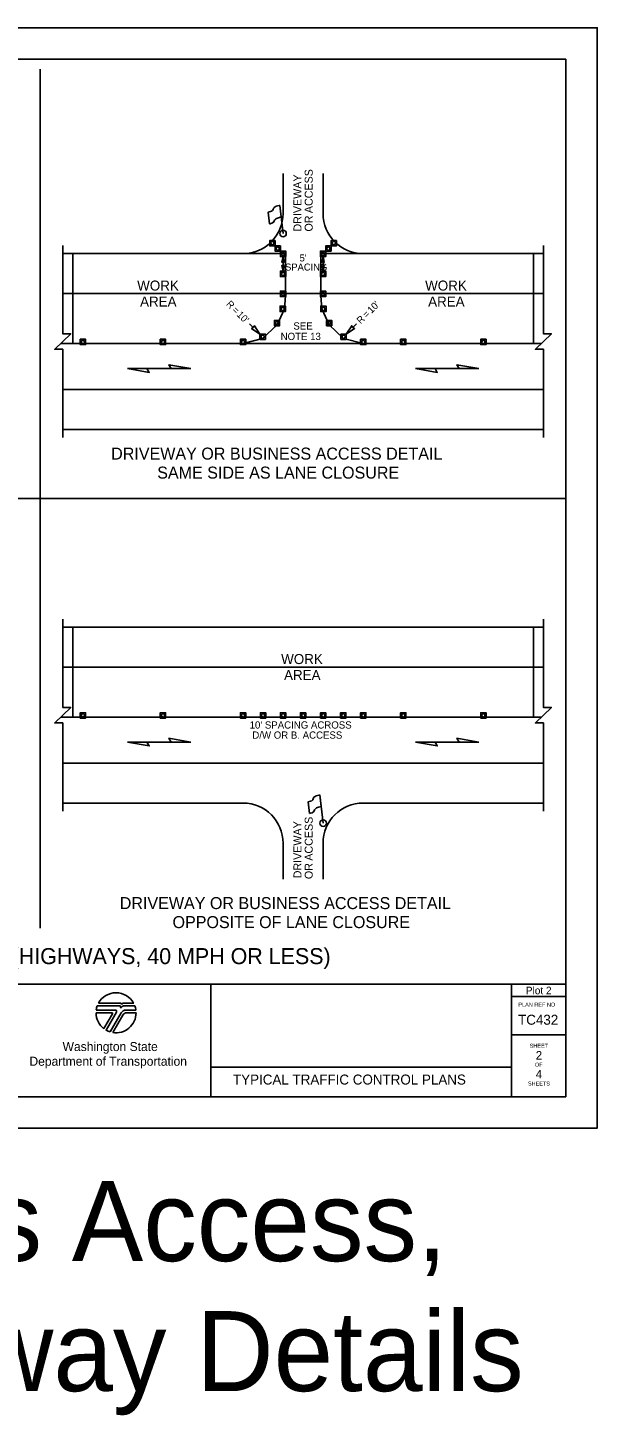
# Model space of a CAD drawing. Extents: x 99999.1 to 100095.7, y 99995 to 100010.7.
# Drawn here: x 100030.38 to 100036.06, y 99996.82 to 100010.69 of the extents above; entities that cross this region are included whole.
import ezdxf

# ---------------------------------------------------------------- set-up
doc = ezdxf.new("R2010")
doc.units = 0
for name, color, linetype in [('RD_ED_DrivewayEdge', 7, 'Continuous'), ('RD_ED_ShoulderPavedEdge', 7, 'Continuous'), ('RD_MK_LineEdgeWhite', 7, 'Continuous'), ('RD_MK_LineSkipCenter', 7, 'Continuous'), ('SH_DE_DetailHeading1Text', 7, 'Continuous'), ('SH_DE_DetailHeading2Text', 7, 'Continuous'), ('SH_GI_PlotLimits', 7, 'Continuous'), ('SH_GI_SheetBorder', 7, 'Continuous'), ('SH_GI_SheetLocationText', 7, 'Continuous'), ('SH_GI_SheetTextInCells', 7, 'Continuous'), ('SH_GI_TitleBlockText', 7, 'Continuous'), ('SH_GI_WSDOTLogo', 7, 'Continuous'), ('TR_WZ_FlaggingStation', 7, 'Continuous'), ('TR_WZ_TrafficCone', 7, 'Continuous'), ('TR_WZ_WorkAreaLabel', 7, 'Continuous'), ('TR_WZ_WorkZoneDetails', 7, 'Continuous'), ('TR_WZ_WorkZoneTextCurrent', 7, 'Continuous')]:
    doc.layers.add(name, color=color, linetype=linetype)

msp = doc.modelspace()

# ---------------------------------------------------------------- linework, layer by layer
at = {"layer": 'RD_ED_DrivewayEdge'}
for p, q in [((100032.925, 100008.83), (100032.925, 100009.23)), ((100033.325, 100008.83), (100033.325, 100009.23)), ((100032.925, 100002.536), (100032.925, 100002.176)), ((100033.325, 100002.536), (100033.325, 100002.176))]:
    msp.add_line(p, q, dxfattribs=at)
for centre, start, end in [((100032.525, 100008.83), 270, 0), ((100033.725, 100008.83), 180, 270), ((100032.525, 100002.536), 0, 90), ((100033.725, 100002.536), 90, 180)]:
    msp.add_arc(centre, 0.4, start, end, dxfattribs=at)
at = {"layer": 'RD_ED_ShoulderPavedEdge'}
for p, q in [((100030.725, 100008.43), (100032.525, 100008.43)), ((100033.725, 100008.43), (100035.525, 100008.43)), ((100030.725, 100006.67), (100035.525, 100006.67)), ((100030.725, 100004.696), (100035.525, 100004.696)), ((100030.725, 100002.936), (100032.525, 100002.936)), ((100033.725, 100002.936), (100035.525, 100002.936))]:
    msp.add_line(p, q, dxfattribs=at)
at = {"layer": 'RD_MK_LineEdgeWhite'}
for p, q in [((100030.725, 100008.03), (100035.525, 100008.03)), ((100030.725, 100007.07), (100035.525, 100007.07)), ((100030.725, 100004.296), (100035.525, 100004.296)), ((100030.725, 100003.336), (100035.525, 100003.336))]:
    msp.add_line(p, q, dxfattribs=at)
at = {"layer": 'RD_MK_LineSkipCenter'}
for points in [[(100035.504, 100007.53), (100030.704, 100007.53)], [(100035.504, 100003.796), (100030.704, 100003.796)]]:
    msp.add_lwpolyline(points, dxfattribs=at)
at = {"layer": 'SH_GI_PlotLimits'}
msp.add_lwpolyline([(100019.062, 99999.687), (100036.062, 99999.687), (100036.062, 100010.687), (100019.062, 100010.687)], close=True, dxfattribs=at)
at = {"layer": 'SH_GI_SheetBorder'}
for p, q in [((100020, 100010.375), (100035.75, 100010.375)), ((100035.75, 100010.375), (100035.75, 100000)), ((100020, 100001.126), (100035.75, 100001.126)), ((100032.205, 100001.126), (100032.205, 100000)), ((100035.208, 100001.126), (100035.208, 100000)), ((100035.208, 100001.001), (100035.75, 100001.001)), ((100035.208, 100000.618), (100035.75, 100000.618)), ((100032.205, 100000.295), (100035.208, 100000.295)), ((100020, 100000), (100035.75, 100000))]:
    msp.add_line(p, q, dxfattribs=at)
at = {"layer": 'SH_GI_WSDOTLogo'}
for p, q in [((100031.059, 100000.866), (100031.25, 100000.866)), ((100031.289, 100000.909), (100031.07, 100000.909)), ((100031.303, 100000.935), (100031.081, 100000.935)), ((100031.433, 100000.935), (100031.335, 100000.935)), ((100031.445, 100000.909), (100031.343, 100000.909)), ((100031.343, 100000.909), (100031.343, 100000.909)), ((100031.356, 100000.866), (100031.456, 100000.866)), ((100031.057, 100000.84), (100031.215, 100000.84)), ((100031.222, 100000.828), (100031.136, 100000.681)), ((100031.261, 100000.846), (100031.157, 100000.667)), ((100031.199, 100000.649), (100031.309, 100000.839)), ((100031.224, 100000.643), (100031.324, 100000.816)), ((100031.365, 100000.839), (100031.457, 100000.839))]:
    msp.add_line(p, q, dxfattribs=at)
for centre, radius, start, end in [((100031.257, 100000.84), 0.2, 28.4787, 151.532), ((100031.257, 100000.84), 0.2, 159.696, 172.5057), ((100031.25, 100000.853), 0.0131, 329.7683, 90), ((100031.289, 100000.895), 0.0148, 327.8418, 89.9985), ((100031.343, 100000.861), 0.0484, 89.9953, 147.8238), ((100031.303, 100000.926), 0.00903, 329.8742, 90.0033), ((100031.356, 100000.812), 0.0542, 90, 149.9974), ((100031.335, 100000.907), 0.0287, 90.0072, 148.1676), ((100031.257, 100000.84), 0.2, 7.4943, 20.2941), ((100031.257, 100000.84), 0.2, 179.9986, 232.8433), ((100031.215, 100000.832), 0.0082, 329.7436, 90), ((100031.257, 100000.84), 0.2, 260.5455, 359.8086), ((100031.365, 100000.792), 0.0476, 90, 150.0543), ((100031.257, 100000.84), 0.2, 239.7929, 253.0448)]:
    msp.add_arc(centre, radius, start, end, dxfattribs=at)
at = {"layer": 'TR_WZ_FlaggingStation'}
for p, q in [((100032.906, 100008.797), (100032.893, 100008.912)), ((100032.925, 100008.63), (100032.893, 100008.911)), ((100032.775, 100008.844), (100032.788, 100008.727)), ((100032.906, 100008.797), (100032.906, 100008.797)), ((100033.175, 100002.949), (100033.188, 100002.832)), ((100033.325, 100002.736), (100033.293, 100003.017)), ((100033.306, 100002.903), (100033.293, 100003.017)), ((100033.306, 100002.903), (100033.306, 100002.903))]:
    msp.add_line(p, q, dxfattribs=at)
for points in [[(100032.893, 100008.912), (100032.887, 100008.91), (100032.869, 100008.907), (100032.856, 100008.903), (100032.846, 100008.897), (100032.837, 100008.892), (100032.832, 100008.885), (100032.827, 100008.877), (100032.827, 100008.871), (100032.821, 100008.862), (100032.811, 100008.854), (100032.798, 100008.849), (100032.775, 100008.844)], [(100032.788, 100008.727), (100032.796, 100008.728), (100032.814, 100008.733), (100032.83, 100008.743), (100032.836, 100008.754), (100032.84, 100008.764), (100032.849, 100008.775), (100032.86, 100008.781), (100032.878, 100008.788), (100032.906, 100008.797)], [(100033.293, 100003.017), (100033.287, 100003.016), (100033.269, 100003.012), (100033.256, 100003.008), (100033.246, 100003.002), (100033.237, 100002.997), (100033.232, 100002.991), (100033.227, 100002.983), (100033.227, 100002.977), (100033.221, 100002.967), (100033.211, 100002.96), (100033.198, 100002.955), (100033.175, 100002.949)], [(100033.188, 100002.832), (100033.196, 100002.834), (100033.214, 100002.838), (100033.23, 100002.849), (100033.236, 100002.859), (100033.24, 100002.87), (100033.249, 100002.88), (100033.26, 100002.887), (100033.278, 100002.894), (100033.306, 100002.903)]]:
    msp.add_lwpolyline(points, dxfattribs=at)
for centre in [(100032.925, 100008.63), (100033.325, 100002.736)]:
    msp.add_circle(centre, 0.0325, dxfattribs=at)
at = {"layer": 'TR_WZ_TrafficCone'}
for points in [[(100032.845, 100008.56), (100032.845, 100008.507), (100032.792, 100008.507), (100032.792, 100008.56), (100032.845, 100008.56)], [(100032.792, 100008.56), (100032.792, 100008.507), (100032.845, 100008.507), (100032.845, 100008.56), (100032.792, 100008.56)], [(100032.898, 100008.507), (100032.898, 100008.454), (100032.845, 100008.454), (100032.845, 100008.507), (100032.898, 100008.507)], [(100032.845, 100008.507), (100032.845, 100008.454), (100032.898, 100008.454), (100032.898, 100008.507), (100032.845, 100008.507)], [(100033.352, 100008.507), (100033.352, 100008.454), (100033.405, 100008.454), (100033.405, 100008.507), (100033.352, 100008.507)], [(100033.405, 100008.507), (100033.405, 100008.454), (100033.352, 100008.454), (100033.352, 100008.507), (100033.405, 100008.507)], [(100033.405, 100008.56), (100033.405, 100008.507), (100033.458, 100008.507), (100033.458, 100008.56), (100033.405, 100008.56)], [(100033.458, 100008.56), (100033.458, 100008.507), (100033.405, 100008.507), (100033.405, 100008.56), (100033.458, 100008.56)], [(100032.898, 100008.454), (100032.952, 100008.454), (100032.952, 100008.4), (100032.898, 100008.4), (100032.898, 100008.454)], [(100032.898, 100008.4), (100032.952, 100008.4), (100032.952, 100008.454), (100032.898, 100008.454), (100032.898, 100008.4)], [(100033.352, 100008.454), (100033.298, 100008.454), (100033.298, 100008.4), (100033.352, 100008.4), (100033.352, 100008.454)], [(100033.352, 100008.4), (100033.298, 100008.4), (100033.298, 100008.454), (100033.352, 100008.454), (100033.352, 100008.4)], [(100032.898, 100008.254), (100032.952, 100008.254), (100032.952, 100008.2), (100032.898, 100008.2), (100032.898, 100008.254)], [(100032.898, 100008.2), (100032.952, 100008.2), (100032.952, 100008.254), (100032.898, 100008.254), (100032.898, 100008.2)], [(100033.352, 100008.254), (100033.298, 100008.254), (100033.298, 100008.2), (100033.352, 100008.2), (100033.352, 100008.254)], [(100033.352, 100008.2), (100033.298, 100008.2), (100033.298, 100008.254), (100033.352, 100008.254), (100033.352, 100008.2)], [(100032.898, 100008.054), (100032.952, 100008.054), (100032.952, 100008), (100032.898, 100008), (100032.898, 100008.054)], [(100032.898, 100008), (100032.952, 100008), (100032.952, 100008.054), (100032.898, 100008.054), (100032.898, 100008)], [(100033.352, 100008.054), (100033.298, 100008.054), (100033.298, 100008), (100033.352, 100008), (100033.352, 100008.054)], [(100033.352, 100008), (100033.298, 100008), (100033.298, 100008.054), (100033.352, 100008.054), (100033.352, 100008)], [(100032.896, 100007.904), (100032.949, 100007.904), (100032.949, 100007.85), (100032.896, 100007.85), (100032.896, 100007.904)], [(100032.896, 100007.85), (100032.949, 100007.85), (100032.949, 100007.904), (100032.896, 100007.904), (100032.896, 100007.85)], [(100033.354, 100007.904), (100033.301, 100007.904), (100033.301, 100007.85), (100033.354, 100007.85), (100033.354, 100007.904)], [(100033.354, 100007.85), (100033.301, 100007.85), (100033.301, 100007.904), (100033.354, 100007.904), (100033.354, 100007.85)], [(100032.838, 100007.762), (100032.891, 100007.762), (100032.891, 100007.708), (100032.838, 100007.708), (100032.838, 100007.762)], [(100032.838, 100007.708), (100032.891, 100007.708), (100032.891, 100007.762), (100032.838, 100007.762), (100032.838, 100007.708)], [(100033.412, 100007.762), (100033.359, 100007.762), (100033.359, 100007.708), (100033.412, 100007.708), (100033.412, 100007.762)], [(100033.412, 100007.708), (100033.359, 100007.708), (100033.359, 100007.762), (100033.412, 100007.762), (100033.412, 100007.708)], [(100030.899, 100007.574), (100030.952, 100007.574), (100030.952, 100007.52), (100030.899, 100007.52), (100030.899, 100007.574)], [(100030.899, 100007.52), (100030.952, 100007.52), (100030.952, 100007.574), (100030.899, 100007.574), (100030.899, 100007.52)], [(100031.699, 100007.574), (100031.752, 100007.574), (100031.752, 100007.52), (100031.699, 100007.52), (100031.699, 100007.574)], [(100031.699, 100007.52), (100031.752, 100007.52), (100031.752, 100007.574), (100031.699, 100007.574), (100031.699, 100007.52)], [(100032.499, 100007.574), (100032.552, 100007.574), (100032.552, 100007.52), (100032.499, 100007.52), (100032.499, 100007.574)], [(100032.499, 100007.52), (100032.552, 100007.52), (100032.552, 100007.574), (100032.499, 100007.574), (100032.499, 100007.52)], [(100032.694, 100007.625), (100032.748, 100007.625), (100032.748, 100007.571), (100032.694, 100007.571), (100032.694, 100007.625)], [(100032.694, 100007.571), (100032.748, 100007.571), (100032.748, 100007.625), (100032.694, 100007.625), (100032.694, 100007.571)], [(100033.556, 100007.625), (100033.502, 100007.625), (100033.502, 100007.571), (100033.556, 100007.571), (100033.556, 100007.625)], [(100033.556, 100007.571), (100033.502, 100007.571), (100033.502, 100007.625), (100033.556, 100007.625), (100033.556, 100007.571)], [(100033.699, 100007.574), (100033.752, 100007.574), (100033.752, 100007.52), (100033.699, 100007.52), (100033.699, 100007.574)], [(100033.699, 100007.52), (100033.752, 100007.52), (100033.752, 100007.574), (100033.699, 100007.574), (100033.699, 100007.52)], [(100034.099, 100007.574), (100034.152, 100007.574), (100034.152, 100007.52), (100034.099, 100007.52), (100034.099, 100007.574)], [(100034.099, 100007.52), (100034.152, 100007.52), (100034.152, 100007.574), (100034.099, 100007.574), (100034.099, 100007.52)], [(100034.899, 100007.574), (100034.952, 100007.574), (100034.952, 100007.52), (100034.899, 100007.52), (100034.899, 100007.574)], [(100034.899, 100007.52), (100034.952, 100007.52), (100034.952, 100007.574), (100034.899, 100007.574), (100034.899, 100007.52)], [(100030.899, 100003.839), (100030.952, 100003.839), (100030.952, 100003.786), (100030.899, 100003.786), (100030.899, 100003.839)], [(100030.899, 100003.786), (100030.952, 100003.786), (100030.952, 100003.839), (100030.899, 100003.839), (100030.899, 100003.786)], [(100031.699, 100003.839), (100031.752, 100003.839), (100031.752, 100003.786), (100031.699, 100003.786), (100031.699, 100003.839)], [(100031.699, 100003.786), (100031.752, 100003.786), (100031.752, 100003.839), (100031.699, 100003.839), (100031.699, 100003.786)], [(100032.499, 100003.839), (100032.552, 100003.839), (100032.552, 100003.786), (100032.499, 100003.786), (100032.499, 100003.839)], [(100032.499, 100003.786), (100032.552, 100003.786), (100032.552, 100003.839), (100032.499, 100003.839), (100032.499, 100003.786)], [(100032.699, 100003.839), (100032.752, 100003.839), (100032.752, 100003.786), (100032.699, 100003.786), (100032.699, 100003.839)], [(100032.699, 100003.786), (100032.752, 100003.786), (100032.752, 100003.839), (100032.699, 100003.839), (100032.699, 100003.786)], [(100032.899, 100003.839), (100032.952, 100003.839), (100032.952, 100003.786), (100032.899, 100003.786), (100032.899, 100003.839)], [(100032.899, 100003.786), (100032.952, 100003.786), (100032.952, 100003.839), (100032.899, 100003.839), (100032.899, 100003.786)], [(100033.099, 100003.839), (100033.152, 100003.839), (100033.152, 100003.786), (100033.099, 100003.786), (100033.099, 100003.839)], [(100033.099, 100003.786), (100033.152, 100003.786), (100033.152, 100003.839), (100033.099, 100003.839), (100033.099, 100003.786)], [(100033.299, 100003.839), (100033.352, 100003.839), (100033.352, 100003.786), (100033.299, 100003.786), (100033.299, 100003.839)], [(100033.299, 100003.786), (100033.352, 100003.786), (100033.352, 100003.839), (100033.299, 100003.839), (100033.299, 100003.786)], [(100033.499, 100003.839), (100033.552, 100003.839), (100033.552, 100003.786), (100033.499, 100003.786), (100033.499, 100003.839)], [(100033.499, 100003.786), (100033.552, 100003.786), (100033.552, 100003.839), (100033.499, 100003.839), (100033.499, 100003.786)], [(100033.699, 100003.839), (100033.752, 100003.839), (100033.752, 100003.786), (100033.699, 100003.786), (100033.699, 100003.839)], [(100033.699, 100003.786), (100033.752, 100003.786), (100033.752, 100003.839), (100033.699, 100003.839), (100033.699, 100003.786)], [(100034.099, 100003.839), (100034.152, 100003.839), (100034.152, 100003.786), (100034.099, 100003.786), (100034.099, 100003.839)], [(100034.099, 100003.786), (100034.152, 100003.786), (100034.152, 100003.839), (100034.099, 100003.839), (100034.099, 100003.786)], [(100034.899, 100003.839), (100034.952, 100003.839), (100034.952, 100003.786), (100034.899, 100003.786), (100034.899, 100003.839)], [(100034.899, 100003.786), (100034.952, 100003.786), (100034.952, 100003.839), (100034.899, 100003.839), (100034.899, 100003.786)]]:
    msp.add_lwpolyline(points, dxfattribs=at)
for centre in [(100032.818, 100008.534), (100032.872, 100008.48), (100033.378, 100008.48), (100033.432, 100008.534), (100032.925, 100008.427), (100033.325, 100008.427), (100032.925, 100008.227), (100033.325, 100008.227), (100032.925, 100008.027), (100033.325, 100008.027), (100032.922, 100007.877), (100033.328, 100007.877), (100032.865, 100007.735), (100033.385, 100007.735), (100030.926, 100007.547), (100031.726, 100007.547), (100032.526, 100007.547), (100032.721, 100007.598), (100033.529, 100007.598), (100033.726, 100007.547), (100034.126, 100007.547), (100034.926, 100007.547), (100030.926, 100003.813), (100031.726, 100003.813), (100032.526, 100003.813), (100032.726, 100003.813), (100032.926, 100003.813), (100033.126, 100003.813), (100033.326, 100003.813), (100033.526, 100003.813), (100033.726, 100003.813), (100034.126, 100003.813), (100034.926, 100003.813)]:
    msp.add_circle(centre, 0.0167, dxfattribs=at)
at = {"layer": 'TR_WZ_WorkZoneDetails'}
for p, q in [((100030.5, 100010.275), (100030.5, 100001.686)), ((100032.925, 100008.346), (100032.925, 100008.308)), ((100033.325, 100008.346), (100033.325, 100008.308)), ((100032.628, 100007.691), (100032.59, 100007.729)), ((100033.622, 100007.691), (100033.66, 100007.729)), ((100031.566, 100007.28), (100031.808, 100007.28)), ((100031.808, 100007.28), (100031.566, 100007.28)), ((100034.443, 100007.28), (100034.684, 100007.28)), ((100034.684, 100007.28), (100034.443, 100007.28)), ((100030.5, 100005.98), (100025.25, 100005.98)), ((100035.75, 100005.98), (100030.5, 100005.98)), ((100031.566, 100003.546), (100031.808, 100003.546)), ((100031.808, 100003.546), (100031.566, 100003.546)), ((100034.443, 100003.546), (100034.684, 100003.546)), ((100034.684, 100003.546), (100034.443, 100003.546))]:
    msp.add_line(p, q, dxfattribs=at)
for points in [[(100030.725, 100006.59), (100030.725, 100007.473), (100030.645, 100007.473), (100030.805, 100007.628), (100030.725, 100007.628), (100030.725, 100008.51)], [(100035.525, 100006.59), (100035.525, 100007.473), (100035.445, 100007.473), (100035.605, 100007.628), (100035.525, 100007.628), (100035.525, 100008.51)], [(100030.725, 100002.856), (100030.725, 100003.738), (100030.645, 100003.738), (100030.805, 100003.893), (100030.725, 100003.893), (100030.725, 100004.776)], [(100035.525, 100002.856), (100035.525, 100003.738), (100035.445, 100003.738), (100035.605, 100003.893), (100035.525, 100003.893), (100035.525, 100004.776)]]:
    msp.add_lwpolyline(points, dxfattribs=at)
for points in [[(100032.948, 100008.43), (100032.948, 100008.207), (100032.948, 100008.007), (100032.939, 100007.877), (100032.939, 100007.877), (100032.939, 100007.877), (100032.865, 100007.718), (100032.865, 100007.718), (100032.865, 100007.718), (100032.721, 100007.581), (100032.526, 100007.53), (100031.529, 100007.53), (100030.949, 100007.53), (100030.825, 100007.53), (100030.825, 100008.43)], [(100032.925, 100008.4), (100032.936, 100008.343), (100032.925, 100008.346), (100032.914, 100008.343)], [(100035.425, 100008.43), (100035.425, 100008.03), (100035.425, 100007.53), (100034.501, 100007.53), (100034.501, 100007.53), (100034.501, 100007.53), (100033.726, 100007.53), (100033.726, 100007.53), (100033.726, 100007.53), (100033.529, 100007.581), (100033.385, 100007.718), (100033.311, 100007.877), (100033.302, 100008.007), (100033.302, 100008.207), (100033.302, 100008.43)], [(100033.325, 100008.4), (100033.336, 100008.343), (100033.325, 100008.346), (100033.314, 100008.343)], [(100032.925, 100008.254), (100032.936, 100008.311), (100032.925, 100008.308), (100032.914, 100008.311)], [(100033.325, 100008.254), (100033.336, 100008.311), (100033.325, 100008.308), (100033.314, 100008.311)], [(100032.694, 100007.625), (100032.611, 100007.681), (100032.628, 100007.691), (100032.639, 100007.708)], [(100033.556, 100007.625), (100033.639, 100007.681), (100033.622, 100007.691), (100033.611, 100007.708)], [(100031.37, 100007.28), (100031.589, 100007.242), (100031.566, 100007.28)], [(100032.004, 100007.28), (100031.785, 100007.319), (100031.808, 100007.28)], [(100034.247, 100007.28), (100034.465, 100007.242), (100034.443, 100007.28)], [(100034.881, 100007.28), (100034.662, 100007.319), (100034.684, 100007.28)], [(100030.825, 100004.696), (100030.825, 100003.796), (100035.425, 100003.796), (100035.425, 100004.696)], [(100031.37, 100003.546), (100031.589, 100003.507), (100031.566, 100003.546)], [(100032.004, 100003.546), (100031.785, 100003.584), (100031.808, 100003.546)], [(100034.247, 100003.546), (100034.465, 100003.507), (100034.443, 100003.546)], [(100034.881, 100003.546), (100034.662, 100003.584), (100034.684, 100003.546)]]:
    msp.add_lwpolyline(points, close=True, dxfattribs=at)

# ---------------------------------------------------------------- texts
at = {"layer": 'SH_DE_DetailHeading1Text'}
msp.add_text('ALTERNATING 1-LANE, 2-WAY TRAFFIC: AFAD-CONTROLLED + TEMP. RUMBLE STRIPS (HIGHWAYS, 40 MPH OR LESS)', height=0.16, rotation=360, dxfattribs=at).set_placement((100021.185, 100001.326))
at = {"layer": 'SH_DE_DetailHeading2Text'}
for s, p in [('DRIVEWAY OR BUSINESS ACCESS DETAIL', (100031.208, 100006.37)), ('SAME SIDE AS LANE CLOSURE', (100031.668, 100006.18)), ('DRIVEWAY OR BUSINESS ACCESS DETAIL', (100031.294, 100001.876)), ('OPPOSITE OF LANE CLOSURE', (100031.821, 100001.686))]:
    msp.add_text(s, height=0.12, rotation=360, dxfattribs=at).set_placement(p)
at = {"layer": 'SH_GI_SheetBorder'}
msp.add_text('PLAN REF NO', height=0.04003, dxfattribs=at).set_placement((100035.275, 100000.901))
at = {"layer": 'SH_GI_SheetLocationText'}
for s, height, p in [('Plot 2', 0.075, (100035.35, 100001.025)), ('Driveway, Business Access,', 0.8, (100021.184, 99998.357)), ('or Intersecting Roadway Details', 0.8, (100020.225, 99997.057))]:
    msp.add_text(s, height=height, dxfattribs=at).set_placement(p)
at = {"layer": 'SH_GI_SheetTextInCells'}
for s, height, p in [('Washington State', 0.09007, (100030.723, 100000.457)), ('SHEET', 0.04, (100035.388, 100000.49)), ('Department of Transportation', 0.09007, (100030.392, 100000.31)), ('OF', 0.04, (100035.441, 100000.301)), ('SHEETS', 0.04, (100035.37, 100000.112))]:
    msp.add_text(s, height=height, dxfattribs=at).set_placement(p)
at = {"layer": 'SH_GI_TitleBlockText'}
for s, height, p in [('TC432', 0.1, (100035.272, 100000.72)), ('2', 0.085, (100035.449, 100000.372)), ('TYPICAL TRAFFIC CONTROL PLANS', 0.1, (100032.425, 100000.122)), ('4', 0.085, (100035.449, 100000.184))]:
    msp.add_text(s, height=height, dxfattribs=at).set_placement(p)
at = {"layer": 'TR_WZ_WorkAreaLabel'}
for s, p in [('WORK', (100031.468, 100008.06)), ('WORK', (100034.344, 100008.06)), ('AREA', (100031.497, 100007.9)), ('AREA', (100034.374, 100007.9)), ('WORK', (100032.906, 100004.326)), ('AREA', (100032.935, 100004.166))]:
    msp.add_text(s, height=0.1, dxfattribs=at).set_placement(p)
at = {"layer": 'TR_WZ_WorkZoneTextCurrent'}
for s, height, rotation, p in [('DRIVEWAY', 0.08, 90, (100033.109, 100008.65)), ('ACCESS', 0.08, 90, (100033.221, 100008.834)), ('OR', 0.08, 90, (100033.221, 100008.65)), ('R', 0.07, 315, (100032.351, 100007.919)), ("10'", 0.07, 45, (100033.808, 100007.827)), ('=', 0.07, 315, (100032.41, 100007.859)), ("10'", 0.07, 315, (100032.457, 100007.813)), ('R', 0.07, 45, (100033.701, 100007.721)), ('=', 0.07, 45, (100033.761, 100007.78)), ('ACCESS', 0.08, 90, (100033.221, 100002.36)), ('DRIVEWAY', 0.08, 90, (100033.109, 100002.184)), ('OR', 0.08, 90, (100033.221, 100002.176))]:
    msp.add_text(s, height=height, rotation=rotation, dxfattribs=at).set_placement(p)
for s, height, p in [("5'", 0.07, (100033.09, 100008.351)), ('SPACING', 0.07, (100032.945, 100008.26)), ('SEE', 0.072, (100033.028, 100007.67)), ('NOTE 13', 0.072, (100032.901, 100007.566)), ("10' SPACING ACROSS", 0.072, (100032.591, 100003.681)), ('D/W OR B. ACCESS', 0.072, (100032.618, 100003.58))]:
    msp.add_text(s, height=height, dxfattribs=at).set_placement(p)

doc.saveas('drawing.dxf')
